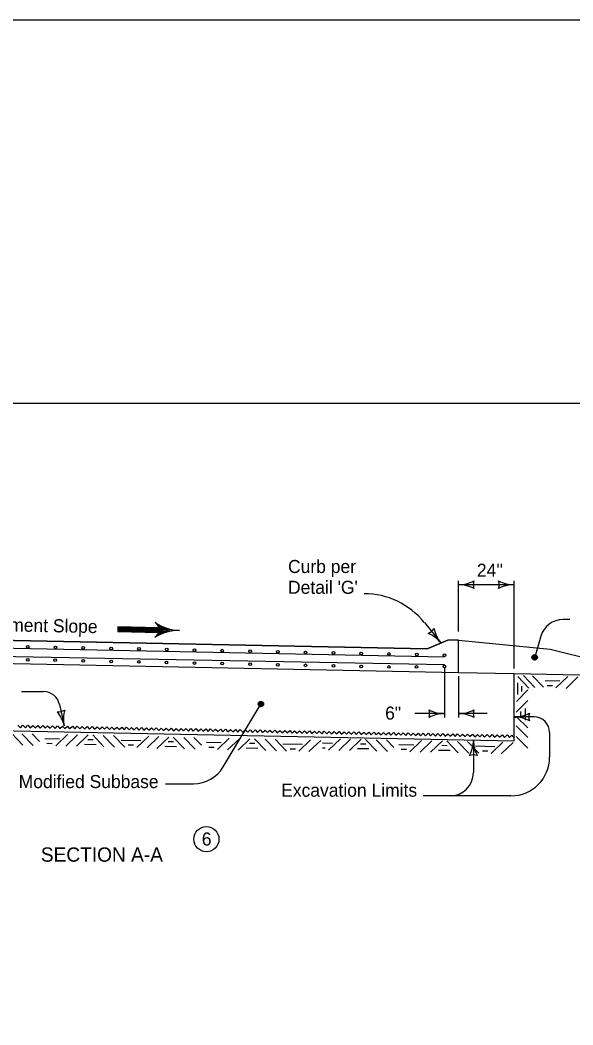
# Model space of a CAD drawing. Extents: x -2135039 to -2124495, y -2139046 to -2132546.
# Drawn here: x -2127278 to -2126601, y -2133778 to -2132546 of the extents above; entities that cross this region are included whole.
import ezdxf

# ---------------------------------------------------------------- set-up
doc = ezdxf.new("R2010")
doc.units = 0
for name, color, linetype in [('BridgeSuperStructureExisting', 7, 'Continuous'), ('dsnAlignmentStation', 7, 'Continuous'), ('dsnStdLabel', 7, 'Continuous'), ('dsnStdLineWork', 7, 'Continuous')]:
    doc.layers.add(name, color=color, linetype=linetype)

msp = doc.modelspace()

# ---------------------------------------------------------------- linework, layer by layer
at = {"layer": 'BridgeSuperStructureExisting'}
for p, q in [((-2126741.2, -2133295.6), (-2126741.2, -2133233.5)), ((-2126673.1, -2133238.2), (-2126741.2, -2133238.2)), ((-2126673.1, -2133340.9), (-2126673.1, -2133233.5)), ((-2126604.6, -2133280.8), (-2126613, -2133280.8)), ((-2127108.1, -2133293.7), (-2127158.2, -2133292.7)), ((-2127108.1, -2133290.7), (-2127108.1, -2133290.7)), ((-2126782.9, -2133284.4), (-2126762.7, -2133309.6)), ((-2126779.5, -2133316.6), (-2127489.7, -2133302.3)), ((-2127489.7, -2133302.3), (-2126779.5, -2133316.6)), ((-2127108.2, -2133296.6), (-2127108.2, -2133296.6)), ((-2126754, -2133306), (-2126779.5, -2133316.6)), ((-2126779.5, -2133316.6), (-2126754, -2133306)), ((-2126741.2, -2133306), (-2126754, -2133306)), ((-2126741.2, -2133306), (-2126754, -2133306)), ((-2126741.2, -2133345.7), (-2126741.2, -2133306)), ((-2126741.2, -2133345.7), (-2126741.2, -2133306)), ((-2126741.2, -2133306), (-2126628.9, -2133317.2)), ((-2126640.2, -2133301.2), (-2126647.8, -2133327.2)), ((-2127489.8, -2133311.8), (-2126758.1, -2133326.5)), ((-2126628.9, -2133317.2), (-2126380.7, -2133379.3)), ((-2127490.3, -2133330.7), (-2126741.2, -2133345.7)), ((-2127489.2, -2133330.7), (-2126741.2, -2133345.7)), ((-2127268.8, -2133328.5), (-2127268.8, -2133328.5)), ((-2127234.7, -2133329.2), (-2127234.7, -2133329.2)), ((-2127200.7, -2133329.9), (-2127200.7, -2133329.9)), ((-2127166.7, -2133330.6), (-2127166.7, -2133330.6)), ((-2127030.3, -2133320.9), (-2127030.3, -2133320.9)), ((-2126996.3, -2133321.6), (-2126996.3, -2133321.6)), ((-2126928.2, -2133323), (-2126928.2, -2133323)), ((-2126894.2, -2133323.6), (-2126894.2, -2133323.6)), ((-2126826.1, -2133325), (-2126826.1, -2133325)), ((-2127132.6, -2133331.2), (-2127132.6, -2133331.2)), ((-2127098.6, -2133331.9), (-2127098.6, -2133331.9)), ((-2127064.6, -2133332.6), (-2127064.6, -2133332.6)), ((-2127030.5, -2133333.3), (-2127030.5, -2133333.3)), ((-2126996.5, -2133334), (-2126996.5, -2133334)), ((-2126962.5, -2133334.7), (-2126962.5, -2133334.7)), ((-2126928.4, -2133335.3), (-2126928.4, -2133335.3)), ((-2126894.4, -2133336), (-2126894.4, -2133336)), ((-2126860.4, -2133336.7), (-2126860.4, -2133336.7)), ((-2126826.3, -2133337.4), (-2126826.3, -2133337.4)), ((-2126758.2, -2133340.2), (-2126758.2, -2133400.9)), ((-2126741.2, -2133345.7), (-2126673.1, -2133347.1)), ((-2126741.2, -2133350.4), (-2126741.2, -2133400.9)), ((-2126673.1, -2133429.5), (-2126673.1, -2133347.1)), ((-2126673.1, -2133347.1), (-2126495.3, -2133350.6)), ((-2126668.6, -2133350.6), (-2126654.8, -2133365)), ((-2126661.4, -2133349.6), (-2126647.6, -2133364)), ((-2126650.6, -2133350), (-2126637.2, -2133363.9)), ((-2126607.3, -2133350.8), (-2126621.8, -2133364.7)), ((-2126594.9, -2133351.3), (-2126609.3, -2133365.2)), ((-2126670.1, -2133381.2), (-2126656, -2133367)), ((-2127276, -2133369.2), (-2127249.2, -2133369.2)), ((-2126670.3, -2133394.2), (-2126656.2, -2133380)), ((-2127229.7, -2133384.9), (-2127223.9, -2133411.3)), ((-2127228.2, -2133391.4), (-2127227.1, -2133396.5)), ((-2127029.1, -2133461.3), (-2126983.1, -2133384.4)), ((-2126758.2, -2133396.2), (-2126794.7, -2133396.2)), ((-2126706, -2133396.2), (-2126741.2, -2133396.2)), ((-2126648.4, -2133400.3), (-2126673.1, -2133400.3)), ((-2126670.3, -2133399.6), (-2126656.2, -2133413.7)), ((-2127489.7, -2133413.1), (-2126673.1, -2133429.5)), ((-2126670.3, -2133411.2), (-2126656.2, -2133425.3)), ((-2127288.6, -2133420.3), (-2127274.7, -2133434.7)), ((-2127275.6, -2133420.8), (-2127261.7, -2133435.2)), ((-2127263.1, -2133420.8), (-2127254, -2133430.3)), ((-2127219.9, -2133421.7), (-2127234.3, -2133435.5)), ((-2127207.5, -2133422.2), (-2127221.9, -2133436)), ((-2127194.5, -2133422.2), (-2127208.9, -2133436.1)), ((-2127189, -2133422.3), (-2127175.2, -2133436.7)), ((-2127176, -2133422.8), (-2127162.2, -2133437.2)), ((-2127163.6, -2133422.8), (-2127149.7, -2133437.2)), ((-2127120.4, -2133423.7), (-2127134.8, -2133437.5)), ((-2127107.9, -2133424.2), (-2127122.4, -2133438)), ((-2127095.9, -2133424.9), (-2127110.3, -2133438.8)), ((-2127090.5, -2133425), (-2127076.6, -2133439.5)), ((-2127077.5, -2133425.5), (-2127063.6, -2133439.9)), ((-2127065, -2133425.5), (-2127055.9, -2133435)), ((-2127021.8, -2133426.4), (-2127036.2, -2133440.3)), ((-2127009.4, -2133426.9), (-2127023.8, -2133440.7)), ((-2126996.4, -2133426.9), (-2127010.8, -2133440.8)), ((-2126990.9, -2133427), (-2126977.1, -2133441.5)), ((-2126977.9, -2133427.5), (-2126964.1, -2133441.9)), ((-2126965.5, -2133427.5), (-2126951.6, -2133442)), ((-2126922.3, -2133428.4), (-2126936.7, -2133442.3)), ((-2126909.8, -2133428.9), (-2126924.3, -2133442.7)), ((-2126885.7, -2133427), (-2126900.2, -2133440.9)), ((-2126873.3, -2133427.5), (-2126887.7, -2133441.4)), ((-2126860.3, -2133427.6), (-2126874.7, -2133441.4)), ((-2126854.9, -2133427.7), (-2126841, -2133442.1)), ((-2126841.9, -2133428.2), (-2126828, -2133442.6)), ((-2126829.4, -2133428.2), (-2126820.3, -2133437.7)), ((-2126786.2, -2133429), (-2126800.6, -2133442.9)), ((-2126773.8, -2133429.5), (-2126788.2, -2133443.4)), ((-2126760.8, -2133429.6), (-2126775.2, -2133443.4)), ((-2126722.8, -2133428.5), (-2126722.8, -2133468.5)), ((-2126670.3, -2133424.2), (-2126656.2, -2133438.4)), ((-2126629.5, -2133419.2), (-2126629.5, -2133449.6)), ((-2126755.3, -2133429.7), (-2126741.5, -2133444.1)), ((-2126742.3, -2133430.2), (-2126728.5, -2133444.6)), ((-2126729.9, -2133430.2), (-2126716, -2133444.6)), ((-2126686.7, -2133431), (-2126701.1, -2133444.9)), ((-2126674.2, -2133431.5), (-2126688.7, -2133445.4)), ((-2127099.9, -2133482), (-2127065.6, -2133482)), ((-2126676.8, -2133496.9), (-2126784.5, -2133496.9))]:
    msp.add_line(p, q, dxfattribs=at)
for points in [[(-2127108.1, -2133290.9), (-2127158.1, -2133289.9), (-2127158.3, -2133295.6), (-2127108.2, -2133296.6), (-2127108.3, -2133291.7), (-2127157.5, -2133290.5), (-2127157.5, -2133295), (-2127109.3, -2133295.8), (-2127109.1, -2133292.4), (-2127156.8, -2133291.3), (-2127156.8, -2133294.3), (-2127109.9, -2133295.2), (-2127109.7, -2133293.1), (-2127156.3, -2133291.9), (-2127156.2, -2133293.6), (-2127110.5, -2133294.5)], [(-2127109.4, -2133287.2), (-2127107.3, -2133290.6), (-2127107.2, -2133295.6), (-2127109.1, -2133299.8), (-2127101.6, -2133296.9), (-2127092.9, -2133294.6), (-2127090.5, -2133294.1), (-2127096.7, -2133292.7), (-2127105.7, -2133289.4), (-2127108.4, -2133287.9), (-2127107.6, -2133298.4), (-2127094.2, -2133294.2), (-2127107.1, -2133290), (-2127106.8, -2133297.3), (-2127097.5, -2133294.1), (-2127105.9, -2133291.8), (-2127106.4, -2133296), (-2127100.5, -2133294.2), (-2127104.9, -2133292.9), (-2127105.2, -2133294.9), (-2127103.1, -2133294.3)], [(-2126648, -2133330.3), (-2126646.9, -2133329.8), (-2126645.2, -2133329.2), (-2126644.8, -2133327.5), (-2126645.1, -2133325.9), (-2126646.2, -2133324.5), (-2126647.8, -2133324.7), (-2126649.6, -2133324.9), (-2126650.4, -2133326.3), (-2126650.6, -2133327.7), (-2126649.5, -2133329.7), (-2126648.3, -2133329.8), (-2126646.5, -2133329.4), (-2126645.1, -2133328.3), (-2126645.1, -2133326.6), (-2126646.3, -2133325.3), (-2126647.8, -2133325.1), (-2126649.6, -2133325.5), (-2126649.8, -2133326.5), (-2126650.2, -2133327.6), (-2126649.4, -2133329.1), (-2126648.1, -2133329), (-2126646.6, -2133328.8), (-2126645.6, -2133328), (-2126646.1, -2133326.5), (-2126647.2, -2133325.7), (-2126648.7, -2133325.6), (-2126649, -2133326.4), (-2126649.5, -2133327.3), (-2126648.8, -2133328.5), (-2126647.7, -2133328.7), (-2126646.7, -2133328.2), (-2126646.7, -2133327.1), (-2126647.2, -2133326.4), (-2126648.2, -2133326.1), (-2126648.7, -2133326.5), (-2126648.9, -2133327.1), (-2126648.4, -2133328), (-2126647.7, -2133328.2), (-2126647.1, -2133327.7), (-2126647.2, -2133327.2), (-2126647.7, -2133326.8), (-2126648.3, -2133326.8), (-2126648.3, -2133327.3), (-2126647.7, -2133327.6)], [(-2126635.1, -2133355.7), (-2126617, -2133356.1)], [(-2126668.5, -2133372.7), (-2126668.5, -2133358.6)], [(-2126663.4, -2133368.9), (-2126663.4, -2133362.4)], [(-2126632.4, -2133361.6), (-2126625.9, -2133361.7)], [(-2126983.3, -2133387.4), (-2126982.2, -2133386.9), (-2126980.5, -2133386.4), (-2126980.1, -2133384.6), (-2126980.4, -2133383), (-2126981.5, -2133381.6), (-2126983.1, -2133381.8), (-2126984.9, -2133382), (-2126985.7, -2133383.4), (-2126985.9, -2133384.9), (-2126984.8, -2133386.8), (-2126983.6, -2133386.9), (-2126981.8, -2133386.5), (-2126980.4, -2133385.4), (-2126980.4, -2133383.7), (-2126981.6, -2133382.4), (-2126983.1, -2133382.3), (-2126984.9, -2133382.6), (-2126985.1, -2133383.6), (-2126985.5, -2133384.8), (-2126984.7, -2133386.2), (-2126983.4, -2133386.2), (-2126981.9, -2133385.9), (-2126980.9, -2133385.1), (-2126981.4, -2133383.7), (-2126982.5, -2133382.8), (-2126984, -2133382.8), (-2126984.3, -2133383.6), (-2126984.8, -2133384.4), (-2126984.1, -2133385.6), (-2126983, -2133385.8), (-2126982.1, -2133385.3), (-2126982, -2133384.3), (-2126982.5, -2133383.5), (-2126983.5, -2133383.2), (-2126984, -2133383.6), (-2126984.2, -2133384.2), (-2126983.7, -2133385.1), (-2126983, -2133385.3), (-2126982.4, -2133384.9), (-2126982.5, -2133384.3), (-2126983, -2133383.9), (-2126983.7, -2133383.9), (-2126983.6, -2133384.4), (-2126983, -2133384.7)], [(-2126659, -2133404), (-2126659, -2133389.8)], [(-2126664.8, -2133400.2), (-2126664.8, -2133393.6)], [(-2127280.5, -2133410.3), (-2127277.5, -2133413.4), (-2127274.4, -2133410.4), (-2127271.4, -2133413.5), (-2127268.4, -2133410.5), (-2127265.4, -2133413.6), (-2127262.3, -2133410.6), (-2127259.3, -2133413.7), (-2127256.3, -2133410.8), (-2127253.3, -2133413.8), (-2127250.2, -2133410.9), (-2127247.2, -2133414), (-2127244.2, -2133411), (-2127241.2, -2133414.1), (-2127238.1, -2133411.1), (-2127235.1, -2133414.2), (-2127232.1, -2133411.2), (-2127229.1, -2133414.3), (-2127226, -2133411.4), (-2127223, -2133414.4), (-2127220, -2133411.5), (-2127218.5, -2133413)], [(-2127218.5, -2133413), (-2127217, -2133414.6), (-2127213.9, -2133411.6), (-2127211, -2133414.7), (-2127207.9, -2133411.7), (-2127204.9, -2133414.8), (-2127201.8, -2133411.8), (-2127198.9, -2133414.9), (-2127195.8, -2133412), (-2127192.8, -2133415.1), (-2127189.7, -2133412.1), (-2127186.8, -2133415.2), (-2127183.7, -2133412.2), (-2127180.7, -2133415.3), (-2127177.6, -2133412.3), (-2127174.7, -2133415.4), (-2127171.6, -2133412.5), (-2127168.6, -2133415.5), (-2127165.5, -2133412.6), (-2127162.6, -2133415.7), (-2127159.5, -2133412.7), (-2127156.5, -2133415.8), (-2127153.4, -2133412.8), (-2127150.5, -2133415.9), (-2127147.4, -2133412.9), (-2127145.9, -2133414.5)], [(-2127145.9, -2133414.5), (-2127144.4, -2133416), (-2127141.3, -2133413.1), (-2127138.4, -2133416.1), (-2127135.3, -2133413.2), (-2127132.3, -2133416.3), (-2127129.2, -2133413.3), (-2127126.3, -2133416.4), (-2127123.2, -2133413.4), (-2127120.2, -2133416.5), (-2127117.1, -2133413.5), (-2127114.2, -2133416.6), (-2127111.1, -2133413.7), (-2127108.1, -2133416.8), (-2127105, -2133413.8), (-2127102.1, -2133416.9), (-2127099, -2133413.9), (-2127096, -2133417), (-2127092.9, -2133414), (-2127090, -2133417.1), (-2127086.9, -2133414.2), (-2127083.9, -2133417.2), (-2127080.8, -2133414.3), (-2127077.9, -2133417.4), (-2127074.8, -2133414.4), (-2127073.3, -2133415.9)], [(-2127073.3, -2133415.9), (-2127071.8, -2133417.5), (-2127068.7, -2133414.5), (-2127065.8, -2133417.6), (-2127062.7, -2133414.6), (-2127059.7, -2133417.7), (-2127056.6, -2133414.8), (-2127053.7, -2133417.8), (-2127050.6, -2133414.9), (-2127047.6, -2133418), (-2127044.6, -2133415), (-2127041.6, -2133418.1), (-2127038.5, -2133415.1), (-2127035.5, -2133418.2), (-2127032.5, -2133415.2), (-2127029.5, -2133418.3), (-2127026.4, -2133415.4), (-2127023.4, -2133418.5), (-2127020.4, -2133415.5), (-2127017.4, -2133418.6), (-2127014.3, -2133415.6), (-2127011.3, -2133418.7), (-2127008.3, -2133415.7), (-2127005.3, -2133418.8), (-2127002.2, -2133415.9), (-2127000.7, -2133417.4)], [(-2127000.7, -2133417.4), (-2126999.2, -2133418.9), (-2126996.2, -2133416), (-2126993.2, -2133419.1), (-2126990.1, -2133416.1), (-2126987.1, -2133419.2), (-2126984.1, -2133416.2), (-2126981.1, -2133419.3), (-2126978, -2133416.3), (-2126975, -2133419.4), (-2126972, -2133416.5), (-2126969, -2133419.5), (-2126965.9, -2133416.6), (-2126963, -2133419.7), (-2126959.9, -2133416.7), (-2126956.9, -2133419.8), (-2126953.8, -2133416.8), (-2126950.9, -2133419.9), (-2126947.8, -2133416.9), (-2126944.8, -2133420), (-2126941.7, -2133417.1), (-2126938.8, -2133420.2), (-2126935.7, -2133417.2), (-2126932.7, -2133420.3), (-2126929.6, -2133417.3), (-2126928.1, -2133418.9)], [(-2127247.7, -2133426.6), (-2127229.6, -2133427)], [(-2127195.1, -2133427.7), (-2127188.6, -2133427.8)], [(-2127154.1, -2133428.5), (-2127130.1, -2133429)], [(-2126928.1, -2133418.9), (-2126926.7, -2133420.4), (-2126923.6, -2133417.4), (-2126920.6, -2133420.5), (-2126917.5, -2133417.6), (-2126914.6, -2133420.6), (-2126911.5, -2133417.7), (-2126908.5, -2133420.8), (-2126905.4, -2133417.8), (-2126902.5, -2133420.9), (-2126899.4, -2133417.9), (-2126896.4, -2133421), (-2126893.3, -2133418), (-2126890.4, -2133421.1), (-2126887.3, -2133418.2), (-2126884.3, -2133421.2), (-2126881.2, -2133418.3), (-2126878.3, -2133421.4), (-2126875.2, -2133418.4), (-2126872.2, -2133421.5), (-2126869.1, -2133418.5), (-2126866.2, -2133421.6), (-2126863.1, -2133418.6), (-2126860.1, -2133421.7), (-2126857, -2133418.8), (-2126855.6, -2133420.3)], [(-2126855.6, -2133420.3), (-2126854.1, -2133421.9), (-2126851, -2133418.9), (-2126848, -2133422), (-2126844.9, -2133419), (-2126842, -2133422.1), (-2126838.9, -2133419.1), (-2126835.9, -2133422.2), (-2126832.8, -2133419.3), (-2126829.9, -2133422.3), (-2126826.8, -2133419.4), (-2126823.8, -2133422.5), (-2126820.7, -2133419.5), (-2126817.8, -2133422.6), (-2126814.7, -2133419.6), (-2126811.7, -2133422.7), (-2126808.7, -2133419.7), (-2126805.7, -2133422.8), (-2126802.6, -2133419.9), (-2126799.6, -2133422.9), (-2126796.6, -2133420), (-2126793.6, -2133423.1), (-2126790.5, -2133420.1), (-2126787.5, -2133423.2), (-2126784.5, -2133420.2), (-2126783, -2133421.8)], [(-2126783, -2133421.8), (-2126781.5, -2133423.3), (-2126778.4, -2133420.3), (-2126775.4, -2133423.4), (-2126772.4, -2133420.5), (-2126769.4, -2133423.6), (-2126766.3, -2133420.6), (-2126763.3, -2133423.7), (-2126760.3, -2133420.7), (-2126757.3, -2133423.8), (-2126754.2, -2133420.8), (-2126751.2, -2133423.9), (-2126748.2, -2133421), (-2126745.2, -2133424), (-2126742.1, -2133421.1), (-2126739.2, -2133424.2), (-2126736.1, -2133421.2), (-2126733.1, -2133424.3), (-2126730, -2133421.3), (-2126727.1, -2133424.4), (-2126724, -2133421.4), (-2126721, -2133424.5), (-2126717.9, -2133421.6), (-2126715, -2133424.6), (-2126711.9, -2133421.7), (-2126710.4, -2133423.2)], [(-2126710.4, -2133423.2), (-2126708.9, -2133424.8), (-2126705.8, -2133421.8), (-2126702.9, -2133424.9), (-2126699.8, -2133421.9), (-2126696.8, -2133425), (-2126693.7, -2133422), (-2126690.8, -2133425.1), (-2126687.7, -2133422.2), (-2126684.7, -2133425.3), (-2126681.6, -2133422.3), (-2126678.7, -2133425.4), (-2126675.6, -2133422.4), (-2126672.6, -2133425.5), (-2126672.4, -2133425.3)], [(-2127245, -2133432.5), (-2127238.5, -2133432.6)], [(-2127199.1, -2133433.5), (-2127184.9, -2133433.8)], [(-2127145.5, -2133434.5), (-2127138.9, -2133434.6)], [(-2127100.5, -2133436.2), (-2127086.3, -2133436.5)], [(-2127096.6, -2133430.4), (-2127090, -2133430.5)], [(-2127049.6, -2133431.3), (-2127031.5, -2133431.7)], [(-2127046.9, -2133437.2), (-2127040.4, -2133437.3)], [(-2127001, -2133438.2), (-2126986.8, -2133438.5)], [(-2126997, -2133432.4), (-2126990.5, -2133432.5)], [(-2126956, -2133433.2), (-2126932, -2133433.7)], [(-2126947.4, -2133439.2), (-2126940.8, -2133439.3)], [(-2126907.6, -2133437.9), (-2126904.3, -2133438)], [(-2126907.5, -2133432.1), (-2126895.4, -2133432.3)], [(-2126864.9, -2133438.8), (-2126850.7, -2133439.1)], [(-2126861, -2133433), (-2126854.4, -2133433.2)], [(-2126814, -2133434), (-2126795.9, -2133434.3)], [(-2126811.3, -2133439.8), (-2126804.8, -2133439.9)], [(-2126765.4, -2133440.8), (-2126751.2, -2133441.1)], [(-2126761.4, -2133435), (-2126754.9, -2133435.2)], [(-2126720.4, -2133435.8), (-2126696.4, -2133436.3)], [(-2126711.8, -2133441.8), (-2126705.2, -2133441.9)]]:
    msp.add_lwpolyline(points, dxfattribs=at)
for centre, radius in [((-2127268.6, -2133314.3), 1.65), ((-2127234.6, -2133315), 1.65), ((-2127200.5, -2133315.6), 1.65), ((-2127166.3, -2133316.3), 1.65), ((-2127132.3, -2133316.7), 1.65), ((-2127098.4, -2133317.7), 1.65), ((-2127064.4, -2133318.4), 1.65), ((-2127030.4, -2133319), 1.65), ((-2126996.3, -2133319.7), 1.65), ((-2126962.3, -2133320.4), 1.65), ((-2127268.6, -2133330.2), 1.65), ((-2127235, -2133330.8), 1.65), ((-2127200.5, -2133331.5), 1.65), ((-2127166.5, -2133332.2), 1.65), ((-2126928.3, -2133321.1), 1.65), ((-2126894.2, -2133321.8), 1.65), ((-2126860.2, -2133322.5), 1.65), ((-2126826.2, -2133323.1), 1.65), ((-2126792.1, -2133323.8), 1.65), ((-2126758.1, -2133324.5), 1.65), ((-2126647.8, -2133327.2), 3.31), ((-2127132.5, -2133332.9), 1.65), ((-2127098.8, -2133333.5), 1.65), ((-2127064.4, -2133334.2), 1.65), ((-2127030.4, -2133334.9), 1.65), ((-2126996.3, -2133335.6), 1.65), ((-2126962.3, -2133336.3), 1.65), ((-2126928.3, -2133337), 1.65), ((-2126894.2, -2133337.7), 1.65), ((-2126860.2, -2133338.3), 1.65), ((-2126826.2, -2133339), 1.65), ((-2126792.5, -2133339), 1.65), ((-2126758.4, -2133338.3), 1.65), ((-2126983.1, -2133384.4), 3.31), ((-2127049.8, -2133550), 15.4)]:
    msp.add_circle(centre, radius, dxfattribs=at)
for centre, radius, start, end in [((-2126741.2, -2133198), 40.2, 270, 298.0725), ((-2126741.2, -2133198), 40.2, 270, 298.0725), ((-2126741.2, -2133278.4), 40.2, 61.9275, 90), ((-2126741.2, -2133278.4), 40.2, 61.9275, 90), ((-2126707.5, -2133238.2), 15.5, 162.2666, 197.7334), ((-2126707.5, -2133238.2), 15.5, 162.2666, 197.7334), ((-2126706.8, -2133238.2), 15.5, 342.2666, 17.7334), ((-2126673.1, -2133198), 40.2, 241.9275, 270), ((-2126706.8, -2133238.2), 15.5, 342.2666, 17.7334), ((-2126673.1, -2133198), 40.2, 241.9275, 270), ((-2126673.1, -2133278.4), 40.2, 90, 118.0725), ((-2126673.1, -2133278.4), 40.2, 90, 118.0725), ((-2126856.6, -2133343.7), 94.5, 38.8378, 90), ((-2126613, -2133309.2), 28.4, 90, 163.739), ((-2127118.4, -2133293.5), 10.7, 300.5647, 57.1354), ((-2127079.6, -2133233.4), 61, 237.1358, 267.1658), ((-2126783.8, -2133283.4), 15.5, 291.1048, 326.5715), ((-2126731.4, -2133284.4), 40.2, 190.7656, 218.8381), ((-2127082, -2133355.2), 61, 90.5343, 120.5643), ((-2126794, -2133334.8), 40.2, 38.8381, 66.9106), ((-2127249.2, -2133389.2), 20, 12.4314, 90), ((-2127231.1, -2133378.4), 15.5, 264.685, 300.1517), ((-2127184.6, -2133402.6), 40.2, 164.3459, 192.4183), ((-2126791.9, -2133396.2), 15.5, 342.2666, 17.7334), ((-2126758.2, -2133356), 40.2, 241.9275, 270), ((-2126741.2, -2133356), 40.2, 270, 298.0725), ((-2126707.5, -2133396.2), 15.5, 162.2666, 197.7334), ((-2127263.1, -2133419.9), 40.2, 12.4183, 40.4908), ((-2126758.2, -2133436.4), 40.2, 90, 118.0725), ((-2126741.2, -2133436.4), 40.2, 61.9275, 90), ((-2126673.1, -2133360.2), 40.2, 270, 298.0725), ((-2126673.1, -2133440.5), 40.2, 61.9275, 90), ((-2126639.5, -2133400.3), 15.5, 162.2666, 197.7334), ((-2126648.4, -2133419.2), 18.9, 0, 90), ((-2126763, -2133428.5), 40.2, 331.9275, 360), ((-2126682.6, -2133428.5), 40.2, 180, 208.0725), ((-2126722.8, -2133462.2), 15.5, 72.2666, 107.7334), ((-2126676.8, -2133449.6), 47.3, 270, 360), ((-2127065.6, -2133439.5), 42.5, 270, 329.1249), ((-2126751.2, -2133468.5), 28.4, 270, 360)]:
    msp.add_arc(centre, radius, start, end, dxfattribs=at)
at = {"layer": 'dsnAlignmentStation'}
msp.add_lwpolyline([(-2127734.4, -2133016), (-2124599.4, -2133016), (-2124599.4, -2135026), (-2127734.4, -2135026)], close=True, dxfattribs=at)
at = {"layer": 'dsnStdLabel'}
msp.add_line((-2126758.2, -2133336.4), (-2127489.8, -2133322.9), dxfattribs=at)
at = {"layer": 'dsnStdLineWork'}
msp.add_lwpolyline([(-2127838.9, -2135130.5), (-2124494.9, -2135130.5), (-2124494.9, -2132546.5), (-2127838.9, -2132546.5)], close=True, dxfattribs=at)

# ---------------------------------------------------------------- texts
at = {"layer": 'BridgeSuperStructureExisting'}
msp.add_text('SECTION A-A', height=17.5, dxfattribs=at).set_placement((-2127252.5, -2133577.6))
at = {"layer": 'dsnStdLabel'}
for s, p in [('Curb per ', (-2126949.8, -2133223.9)), ("24''", (-2126718.6, -2133228.5)), ("Detail 'G'", (-2126949.8, -2133249.4)), ('6"', (-2126830.9, -2133403.5)), ('Modified Subbase', (-2127279.6, -2133487.4)), ('Excavation Limits', (-2126958.2, -2133498)), ('6', (-2127055.4, -2133557.8))]:
    msp.add_text(s, height=16, dxfattribs=at).set_placement(p)
msp.add_text('Normal Pavement Slope', height=16, rotation=358.8502, dxfattribs=at).set_placement((-2127415, -2133292.9))

doc.saveas('drawing.dxf')
